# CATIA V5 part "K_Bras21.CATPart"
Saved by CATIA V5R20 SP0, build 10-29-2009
Part number: Bras21
Publications: "demilargeur_bras21", "epaisseur_bras21"
Bounding box of the stored display mesh (mm): x 4 to 44, y -5.003 to 5, z -91.99 to 4.99
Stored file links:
  G:\Khaled_CFAO_2011\SIL\SIL_GR2\zthiebault\Khaled\CAD_ThinkMOTION\K_Bras21.CATPart
  F:\Projet Thinkmotion\Catia\FINAL\HabillageFinal.CATProduct
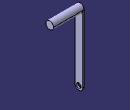
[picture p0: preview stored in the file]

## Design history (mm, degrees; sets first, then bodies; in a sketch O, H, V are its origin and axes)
Parameters
  demilargeur_bras21 = 5 mm
  epaisseur_bras21 = 2 mm
External parameters (linked from other documents)
  External.epaisseur_coude = 2 mm
  `External.épaisseur_bras24` = 2 mm
  External.rayonpivot_bras21 = 3 mm
Set1
  Point1 "Point_base_bras21_haut": linked copy from another document
  Point2 "Point_base_bras21_bas": linked copy from another document
  Line1 "Droite_base_bras21": linked copy from another document
Body1 (main body)
  Sketch1 on yz-plane, origin (0, 0, 0), H (0, 1, 0), V (0, 0, 1)
    point P1 (-5, 0.0002)
    line L1 (-5, 0.0002) -> (-5.0027, -86.9998)
    arc A1 centre (-0.0027, -87) radius 5 from (-5.0027, -86.9998) to (4.9973, -87.0002) ccw
    point P3 (-0.0027, -87)
    line L2 (4.9973, -87.0002) -> (5, -0.0002)
    arc A2 centre (0, 0) radius 5 from (5, -0.0002) to (-5, 0.0002) ccw
    point P6 (0, 0)
    point P7 (-5, 0.0002)
    reference projected point E1 (0, 0) from Point1
    reference projected point E2 (-0.0027, -87) from Point2
    reference projected line E3 (-0.0027, -87) -> (0, 0) from Line1
    radius A2 = 5 {= demilargeur_bras21}
    tangency: A1 L1, L2 A1, A2 L2, L1 A2
    coincidence: P7 P1, P6 E1, P3 E2
    parallelism: E3 L1, L1 L2
  Pad1: profile Sketch1, direction (1, 0, 0), length 4 {= External.epaisseur_coude +`External.épaisseur_bras24`}, opposite side length -6 {= -External.epaisseur_coude -`External.épaisseur_bras24` -epaisseur_bras21}
  Sketch2 on end face of Pad1, origin (4, 0, 0), H (0, -1, 0), V (0, 0, 1)
    circle A1 centre (0, 0) radius 5
    reference projected arc E1 centre (0, 0) radius 5 from (5, 0.0002) to (-5, -0.0002) ccw from edge [end face of Pad1 | face of Pad1 from Sketch1.A2]
    reference projected arc E2 centre (0, 0) radius 5 from (5, 0.0002) to (-5, -0.0002) ccw from edge [end face of Pad1 | face of Pad1 from Sketch1.A2]
    concentricity: E1 A1
    coincidence: E2 A1
  Pad2: profile Sketch2, direction (1, 0, 0), length 40
  Sketch3 on start face of Pad1, origin (6, 2.9444, -74.9557), H (0, 1, 0), V (0, 0, 1)
    point P1 (-2.9471, -12.0443)
    reference projected arc E1 centre (-2.9471, -12.0443) radius 5 from (-7.9471, -12.0442) to (2.0529, -12.0445) ccw from edge [face of Pad1 from Sketch1.A1 | start face of Pad1]
    concentricity: P1 E1
  Hole1: placed by Sketch3, at (6, -0.0027, -87) direction (-1, 0, 0), diameter 6 {= External.rayonpivot_bras21 *2}, depth 10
